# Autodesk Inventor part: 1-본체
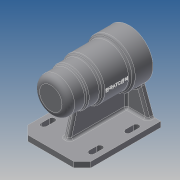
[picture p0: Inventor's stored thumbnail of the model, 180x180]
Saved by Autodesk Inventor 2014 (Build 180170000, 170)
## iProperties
Created: 2017-09
Part Number: 1-본체
Material: Generic
Document SubType Name: Modeling
Designer: kb542-22
Density: 1 g/cm^3
Appearance: Default
Author: kb542-22
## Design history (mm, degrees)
sketch "스케치1"
  geometry: L1 (56, 0)-(-56, 0); L2 (56, 21)-(41, 21); L3 (41, 21)-(41, 24); L4 (41, 24)-(-13, 24); L5 (-13, 24)-(-13, 21); L6 (-13, 21)-(-25, 21); L7 (-25, 21)-(-25, 17.5); L8 (-25, 17.5)-(-43, 17.5); L9 (-43, 17.5)-(-43, 16); L10 (-43, 16)-(-47, 16); L11 (-47, 16)-(-47, 10.5); L12 (-47, 10.5)-(-50, 10.5); L13 (-50, 10.5)-(-50, 0); L14 (-56, 0)-(-56, 25); L15 (-56, 25)-(-32.5, 25); L16 (-31, 27)-(-13.25, 27); L17 (-11, 30)-(25, 30); L18 (28, 34)-(56, 34); L19 (56, 34)-(56, 21); L20 (28, 34)-(28, 30); L21 (28, 30)-(25, 30); L22 (-13.25, 27)-(-11, 27); L23 (-11, 27)-(-11, 30); L24 (-32.5, 25)-(-31, 25); L25 (-31, 25)-(-31, 27); 2 further points
  constraints: 50 end point, 16 parallel, 7 perpendicular, 1 coincident, 1 collinear, 1 horizontal, 1 midpoint, 1 point on line, 1 vertical alignment
  dimensions: "d0" = 42 diameter of L2 L1; "d1" = 48 diameter of L4 L1; "d2" = 42 diameter of L6 L1; "d3" = 35 diameter of L8 L1; "d4" = 32 diameter of L10 L1; "d5" = 21 diameter of L12 L1; "d6" = 50 diameter of L15 L1; "d7" = 54 diameter of L16.start L1; "d8" = 60 diameter of L17.start L1; "d9" = 68 diameter of L18 L1; "d10" = 15 distance of L2.start L2.end; "d11" = 54 distance of L3.end L4.end; "d12" = 12 distance of L5.end L6.end; "d13" = 18 distance of L7.end L8.end; "d14" = 4 distance of L9.end L10.end; "d15" = 3 distance of L11.end L12.end; "d16" = 112 distance between parallel lines of L19 L14; "d75" = 25 distance between parallel lines of L25 L14; "d76" = 45 distance between parallel lines of L23 L14; "d77" = 84 distance between parallel lines of L20 L14
revolve "회전1" sketch "스케치1" stored, may be unused: angle "d22" = 90 deg
node "작업 평면1"
sketch "스케치2"
  geometry: L1 (-56, 45)-(56, 45); L2 (56, 45)-(56, -45); L3 (56, -45)-(-56, -45); L4 (-56, -45)-(-56, 45); L5 (56, -34)-(56, 34) reference; 2 further points
  constraints: 8 end point, 2 parallel, 1 collinear, 1 horizontal, 1 horizontal alignment, 1 midpoint, 1 perpendicular
  dimensions: "d24" = 112 distance of L1.start L1.end; "d25" = 90 distance of L1.end L2.end
extrude "돌출1" join sketch "스케치2" distance "d26" = 8; taper "d27" = 0 deg
node "작업 평면2"
sketch "스케치3"
  geometry: L1 (45, -62)-(-45, -62) reference; L2 (21.9, -26.008)-(35, -62); L3 (-21.9, -26.008)-(-35, -62); L4 (45, -70)-(45, -62) reference; L5 (-45, -70)-(-45, -62) reference; A1 r 34 centre (0, 0) between (21.9, -26.008) and (-21.9, -26.008) reference; 1 further point
  constraints: 4 end point, 2 point on circle, 2 point on line
  dimensions: "d30" = 110 deg angle of L1 L2; "d31" = 110 deg angle of L1 L3; "d32" = 10 distance from line of L4 L2.end; "d33" = 10 distance from line of L5 L3.end
extrude "돌출2" join sketch "스케치3" distance "d34" = 8; taper "d35" = 0 deg
sketch "스케치4"
  geometry: L1 (56, -25)-(31, -25) reference; L2 (31, -27)-(11, -27) reference; L3 (11, -30)-(-28, -30) reference; L4 (-28, -34)-(-48, -34) reference; L5 (-56, -62)-(56, -62) reference; L6 (24.622, -27)-(34, -62); L7 (56, -70)-(56, -62) reference; 1 further point
  constraints: 2 end point, 2 point on line
  dimensions: "d36" = 22 distance from line of L7 L6.end; "d37" = 105 deg angle of L5 L6
feature "리브1" sketch "스케치4" dims "d38" = 1, "d39" = 8, "d40" = 0, "d41" = 0, "d42" = 1, "d43" = 1
sketch "스케치5"
  geometry: L1 (-8, 80)-(-8, 90) reference; L2 (-70, 45)-(-96, 45); L3 (-70, 45)-(-57, 22.483); C1 r 21 at (-70, 45) reference; A1 r 26 centre (-70, 45) between (-96, 45) and (-57, 22.483); 1 further point
  constraints: 4 end point, 2 coincident, 2 point on circle, 1 centre point, 1 perpendicular
  dimensions: "d44" = 52 diameter of A1; "d45" = 120 deg angle of L2 L3
hole "구멍1" sketch "스케치5" at (-96, 45) diameter "d46" = 3.242; stored, may be unused: countersink angle "d50" = 90 deg, drill point angle "d52" = 118 deg; dims "d47" = 8, "d48" = 4, "d49" = 2, "d51" = 11
node "작업 평면3"
sketch "스케치6"
  geometry: L1 (29.5, -26.008)-(29.5, 34) reference; 2 further points
  constraints: 1 horizontal alignment, 1 other
  dimensions: "d57" = 48 distance from line of point (-18.5, 0) L1
feature "엠보싱1" sketch "스케치6" dims "d0" = 42, "d1" = 48, "d2" = 42, "d3" = 35, "d4" = 32, "d5" = 21, "d6" = 50, "d7" = 54, "d8" = 60, "d9" = 68, "d10" = 15, "d11" = 54, "d12" = 12, "d13" = 18, "d14" = 4, "d15" = 3, "d16" = 112, "d59" = 0.5, "d60" = 0, "d75" = 25, "d76" = 45, "d77" = 84
sketch "스케치7"
  geometry: L1 (48, -4)-(-34, -4) reference; L2 (56, -45)-(56, -35) reference; L3 (32, -34)-(20, -34); L4 (32, -30)-(20, -30); L5 (20, -38)-(32, -38); L6 (-20, -34)-(-32, -34); L7 (-20, -30)-(-32, -30); L8 (-32, -38)-(-20, -38); L9 (56, 45)-(56, -45) reference; L10 (-56, -45)-(-56, 45) reference; L11 (56, 0)-(-56, 0); A1 r 4 centre (32, -34) between (32, -38) and (32, -30); A2 r 4 centre (20, -34) between (20, -30) and (20, -38); A3 r 4 centre (-20, -34) between (-20, -38) and (-20, -30); A4 r 4 centre (-32, -34) between (-32, -30) and (-32, -38); 3 further points
  constraints: 18 end point, 8 point on circle, 8 tangent, 4 centre point, 4 midpoint, 4 parallel, 1 collinear
  dimensions: "d61" = 12 distance of L3.end L3.start; "d62" = 24 distance from line of L2 L3.start; "d63" = 4 radius of A2; "d64" = 12 distance of L6.end L6.start; "d65" = 40 distance of L3.end L6.start; "d67" = 4 radius of A3; "d68" = 34 distance from line of L11 L6.end
extrude "돌출3" cut sketch "스케치7" stored distance "d69" = 8; taper "d70" = 0 deg
chamfer "모따기1" distance "d71" = 12; stored, may be unused: second distance "d72" = 2, angle "d73" = 45 deg
fillet "모깎기1" dims "d74" = 9
fillet "모깎기2" dims "d78" = 3
fillet "모깎기3" dims "d79" = 3
fillet "모깎기4" dims "d80" = 3
fillet "모깎기5" dims "d81" = 3
fillet "모깎기6" dims "d82" = 3
fillet "모깎기7" dims "d83" = 0.3
chamfer "모따기2" distance "d84" = 1; stored, may be unused: second distance "d85" = 2, angle "d86" = 45 deg
node "솔리드1"
pattern_circular "원형 패턴1" dims angle "d54" = 360 deg
mirror "대칭1"
other parameters: "d28" = 48
